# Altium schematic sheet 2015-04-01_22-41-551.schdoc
size 469 x 147 mm; SheetNumber: 1; SheetTotal: 1
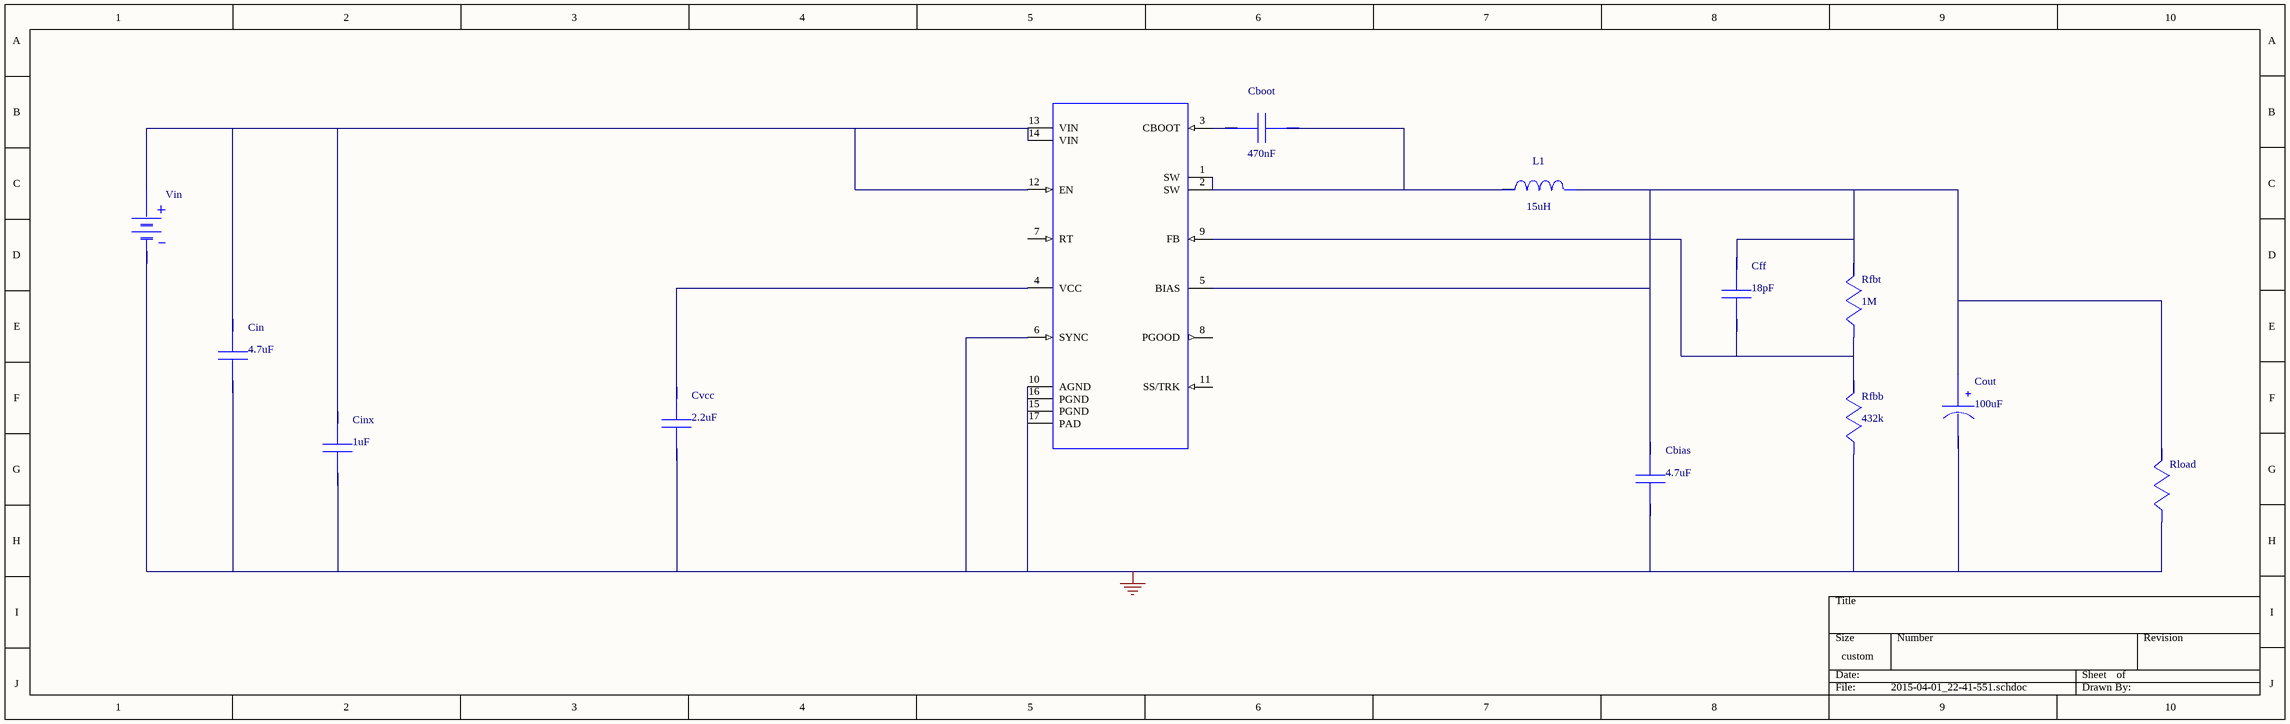
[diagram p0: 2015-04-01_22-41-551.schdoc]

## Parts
Cbias  value 4.7uF  (hidden comment: JMK212BJ475KG-T)
Cboot  value 470nF  (hidden comment: GMK212BJ474KG-T)
Cff  value 18pF  (hidden comment: C0805C180M3GACTU)
Cin  value 4.7uF  (hidden comment: GRM32ER71H475KA88L)
Cinx  value 1uF  (hidden comment: C3216X5R1H105K)
Cout  value 100uF  (hidden comment: 6TPG100M)
Cvcc  value 2.2uF  (hidden comment: C0603C225K9PACTU)
L1  value 15uH  (hidden comment: VLP8040T-150M)
Rfbb  value 432k  (hidden comment: CRCW0402432KFKED)
Rfbt  value 1M  (hidden comment: CRCW04021M00FKED)
Rload  WB_LOAD_RESISTOR  (value not drawn)
U1  LM43602PWPR  (value not drawn)
Vin  WB_BATTERY  (value not drawn)

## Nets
0: Cbias.2 Cin.2 Cinx.2 Cout.2(-) Cvcc.2 Rfbb.2 Rload.2 U1.6(SYNC) U1.10(AGND) U1.15(PGND) U1.16(PGND) U1.17(PAD) Vin.2(-)
NetCbias_1: Cbias.1 Cff.1 Cout.1(+) L1.2 Rfbt.1 Rload.1 U1.5(BIAS)
NetCboot_1: Cboot.1 L1.1 U1.1(SW) U1.2(SW)
NetCboot_2: Cboot.2 U1.3(CBOOT)
NetCff_2: Cff.2 Rfbb.1 Rfbt.2 U1.9(FB)
NetCin_1: Cin.1 Cinx.1 U1.12(EN) U1.13(VIN) U1.14(VIN) Vin.1(+)
NetCvcc_1: Cvcc.1 U1.4(VCC)

Not connected (* = marked no-connect by the designer): U1 7(RT) 8(PGOOD) 11(SS/TRK)

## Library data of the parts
Cbias = JMK212BJ475KG-T: Manufacturer Name: Taiyo Yuden
Cboot = GMK212BJ474KG-T: Manufacturer Name: Taiyo Yuden
Cff = C0805C180M3GACTU: Manufacturer Name: Kemet
Cin = GRM32ER71H475KA88L: GRM32ER71H475KA8; Manufacturer Name: MuRata
Cinx = C3216X5R1H105K: Manufacturer Name: TDK
Cout = 6TPG100M: Manufacturer Name: Panasonic
Cvcc = C0603C225K9PACTU: Manufacturer Name: Kemet
L1 = VLP8040T-150M: Unknown; Manufacturer Name: TDK
Rfbb = CRCW0402432KFKED: Manufacturer Name: Vishay-Dale
Rfbt = CRCW04021M00FKED: Manufacturer Name: Vishay-Dale
Rload = WB_LOAD_RESISTOR: Value: UNLISTED
U1 = LM43602PWPR: Manufacturer Name: Texas Instruments
Vin = WB_BATTERY: Value: UNLISTED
